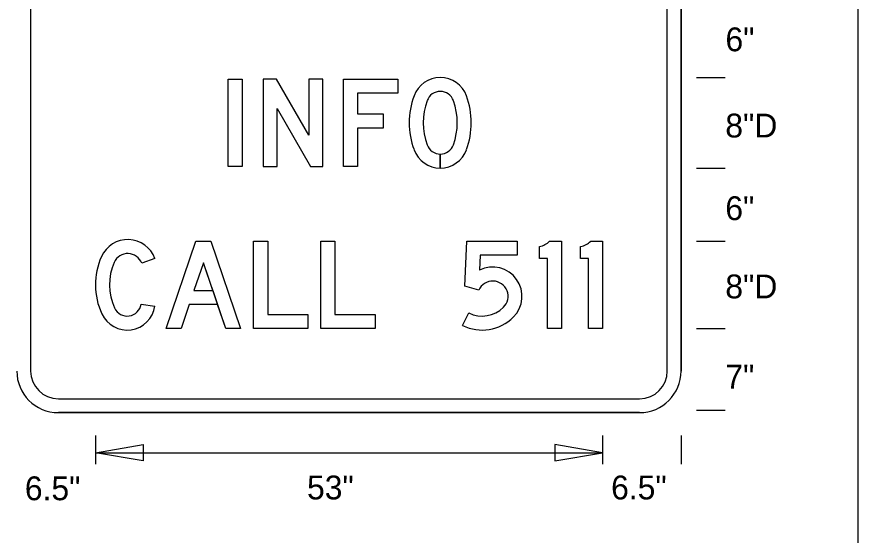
# Model space of a CAD drawing. Extents: x 0 to 770, y 0 to 495.
# Drawn here: x 453.9 to 577.5, y 337 to 413.1 of the extents above; entities that cross this region are included whole.
import ezdxf

# ---------------------------------------------------------------- set-up
doc = ezdxf.new("R2010")
doc.units = 0
for name, color, linetype in [('Default', 7, 'Continuous'), ('Dimension', 7, 'Continuous'), ('GSBWFill', 7, 'Continuous'), ('GSColorFill', 7, 'Continuous'), ('GSDims', 7, 'Continuous'), ('GSOutline', 7, 'Continuous'), ('SheetLines_dp', 7, 'Continuous'), ('TextStructures', 7, 'Continuous')]:
    doc.layers.add(name, color=color, linetype=linetype)

msp = doc.modelspace()

# ---------------------------------------------------------------- linework, layer by layer
at = {"layer": 'Default'}
for p, q in [((455.91, 470.91), (455.91, 361.11)), ((549.45, 361.11), (549.45, 470.91)), ((551.48, 361.11), (551.48, 470.91)), ((551.48, 470.91), (551.48, 361.11)), ((459.98, 357.05), (545.38, 357.05)), ((459.98, 355.01), (545.38, 355.01)), ((545.38, 355.01), (459.98, 355.01))]:
    msp.add_line(p, q, dxfattribs=at)
for centre, radius, start, end in [((459.98, 361.11), 6.1, 180, 270), ((459.98, 361.11), 6.1, 180, 270), ((459.98, 361.11), 4.07, 180, 270), ((545.38, 361.11), 6.1, 270, 0), ((545.38, 361.11), 6.1, 270, 0), ((545.38, 361.11), 4.07, 270, 0)]:
    msp.add_arc(centre, radius, start, end, dxfattribs=at)
at = {"layer": 'Dimension'}
for points in [[(465.43, 349.12), (472.45, 350.31), (472.45, 347.93)], [(539.93, 349.12), (532.91, 350.31), (532.91, 347.93)]]:
    msp.add_lwpolyline(points, close=True, dxfattribs=at)
at = {"layer": 'GSBWFill'}
for p, q in [((516.1, 390.93), (516.1, 392.99)), ((516.1, 392.99), (516.1, 390.93)), ((474.17, 377.64), (472.23, 376.94)), ((472.13, 370.94), (474.17, 370.64)), ((519.38, 367.79), (520.28, 369.64)), ((520.28, 369.64), (520.28, 369.64))]:
    msp.add_line(p, q, dxfattribs=at)
for points in [[(484.95, 404), (487, 404), (487, 391.16), (484.95, 391.16)], [(498.82, 391.16), (498.82, 404), (496.77, 404), (496.77, 395.75), (492.05, 404), (490.09, 404), (490.09, 391.16), (492.14, 391.16), (492.14, 399.7), (497.02, 391.16)], [(509.87, 404), (509.87, 401.95), (503.96, 401.95), (503.96, 398.87), (507.69, 398.87), (507.69, 396.81), (503.96, 396.81), (503.96, 391.16), (501.9, 391.16), (501.9, 404)], [(475.84, 367.36), (480.2, 380.21), (482.39, 380.21), (486.75, 367.36), (484.58, 367.36), (481.29, 377.03), (479.91, 372.95), (482.68, 372.95), (483.38, 370.89), (479.21, 370.89), (478.01, 367.36)], [(490.74, 369.42), (496.64, 369.42), (496.64, 367.36), (488.68, 367.36), (488.68, 380.21), (490.74, 380.21)], [(500.63, 369.42), (506.53, 369.42), (506.53, 367.36), (498.57, 367.36), (498.57, 380.21), (500.63, 380.21)]]:
    msp.add_lwpolyline(points, close=True, dxfattribs=at)
for points in [[(521.76, 373.01), (519.7, 373.59), (520.02, 380.21), (527.41, 380.21), (527.41, 378.15), (521.98, 378.15), (521.87, 375.92)], [(532.16, 380.21), (533.89, 380.21), (533.89, 367.36), (531.84, 367.36), (531.84, 377.64), (530.68, 377.64), (530.68, 379.42)], [(538.2, 380.21), (539.93, 380.21), (539.93, 367.36), (537.88, 367.36), (537.88, 377.64), (536.72, 377.64), (536.72, 379.42)]]:
    msp.add_lwpolyline(points, dxfattribs=at)
for centre, radius, start, end in [((470.18, 376.19), 4.24, 20.0236, 155.9453), ((530.33, 381.87), 2.47, 278.1148, 317.6823), ((536.37, 381.87), 2.47, 278.1148, 317.6823), ((470.18, 376.19), 2.18, 20.0236, 155.9453), ((475.58, 373.78), 10.15, 155.9453, 204.848), ((475.58, 373.78), 8.09, 155.9453, 204.848), ((523.81, 372.08), 4.3, 314.4153, 116.7914), ((523.81, 372.08), 2.25, 314.4153, 155.5257), ((470.1, 371.25), 2.06, 204.848, 351.506), ((470.1, 371.25), 4.11, 204.848, 351.506), ((522.24, 373.69), 4.5, 244.1304, 314.4153), ((522.24, 373.69), 6.55, 244.1304, 314.4153)]:
    msp.add_arc(centre, radius, start, end, dxfattribs=at)
for centre, major_axis, start_param, end_param in [((516.1, 400.12), (0, 4.11), 5.063177, 7.503193), ((516.1, 400.12), (0, 2.06), 5.063177, 7.503193), ((523.03, 397.58), (0, 11.49), 1.220008, 1.921585), ((523.03, 397.58), (0, 9.44), 1.220008, 1.921585), ((509.16, 397.58), (0, 9.44), 4.361601, 5.063177), ((509.16, 397.58), (0, 11.49), 4.361601, 5.063177), ((516.1, 395.04), (0, 4.11), 1.921585, 3.141593), ((516.1, 395.04), (0, 2.06), 1.921585, 3.141593), ((516.1, 395.04), (0, 2.06), 3.141905, 4.361601), ((516.1, 395.04), (0, 4.11), 3.141749, 4.361601)]:
    msp.add_ellipse(centre, major_axis=major_axis, ratio=0.999993, start_param=start_param, end_param=end_param, dxfattribs=at)
at = {"layer": 'GSColorFill'}
for p, q in [((516.1, 390.93), (516.1, 392.99)), ((516.1, 392.99), (516.1, 390.93)), ((474.17, 377.64), (472.23, 376.94)), ((472.13, 370.94), (474.17, 370.64)), ((519.38, 367.79), (520.28, 369.64)), ((520.28, 369.64), (520.28, 369.64))]:
    msp.add_line(p, q, dxfattribs=at)
for points in [[(484.95, 404), (487, 404), (487, 391.16), (484.95, 391.16)], [(498.82, 391.16), (498.82, 404), (496.77, 404), (496.77, 395.75), (492.05, 404), (490.09, 404), (490.09, 391.16), (492.14, 391.16), (492.14, 399.7), (497.02, 391.16)], [(509.87, 404), (509.87, 401.95), (503.96, 401.95), (503.96, 398.87), (507.69, 398.87), (507.69, 396.81), (503.96, 396.81), (503.96, 391.16), (501.9, 391.16), (501.9, 404)], [(475.84, 367.36), (480.2, 380.21), (482.39, 380.21), (486.75, 367.36), (484.58, 367.36), (481.29, 377.03), (479.91, 372.95), (482.68, 372.95), (483.38, 370.89), (479.21, 370.89), (478.01, 367.36)], [(490.74, 369.42), (496.64, 369.42), (496.64, 367.36), (488.68, 367.36), (488.68, 380.21), (490.74, 380.21)], [(500.63, 369.42), (506.53, 369.42), (506.53, 367.36), (498.57, 367.36), (498.57, 380.21), (500.63, 380.21)]]:
    msp.add_lwpolyline(points, close=True, dxfattribs=at)
for points in [[(521.76, 373.01), (519.7, 373.59), (520.02, 380.21), (527.41, 380.21), (527.41, 378.15), (521.98, 378.15), (521.87, 375.92)], [(532.16, 380.21), (533.89, 380.21), (533.89, 367.36), (531.84, 367.36), (531.84, 377.64), (530.68, 377.64), (530.68, 379.42)], [(538.2, 380.21), (539.93, 380.21), (539.93, 367.36), (537.88, 367.36), (537.88, 377.64), (536.72, 377.64), (536.72, 379.42)]]:
    msp.add_lwpolyline(points, dxfattribs=at)
for centre, radius, start, end in [((470.18, 376.19), 4.24, 20.0236, 155.9453), ((530.33, 381.87), 2.47, 278.1148, 317.6823), ((536.37, 381.87), 2.47, 278.1148, 317.6823), ((470.18, 376.19), 2.18, 20.0236, 155.9453), ((475.58, 373.78), 10.15, 155.9453, 204.848), ((475.58, 373.78), 8.09, 155.9453, 204.848), ((523.81, 372.08), 4.3, 314.4153, 116.7914), ((523.81, 372.08), 2.25, 314.4153, 155.5257), ((470.1, 371.25), 2.06, 204.848, 351.506), ((470.1, 371.25), 4.11, 204.848, 351.506), ((522.24, 373.69), 4.5, 244.1304, 314.4153), ((522.24, 373.69), 6.55, 244.1304, 314.4153)]:
    msp.add_arc(centre, radius, start, end, dxfattribs=at)
for centre, major_axis, start_param, end_param in [((516.1, 400.12), (0, 4.11), 5.063177, 7.503193), ((516.1, 400.12), (0, 2.06), 5.063177, 7.503193), ((523.03, 397.58), (0, 11.49), 1.220008, 1.921585), ((523.03, 397.58), (0, 9.44), 1.220008, 1.921585), ((509.16, 397.58), (0, 9.44), 4.361601, 5.063177), ((509.16, 397.58), (0, 11.49), 4.361601, 5.063177), ((516.1, 395.04), (0, 4.11), 1.921585, 3.141593), ((516.1, 395.04), (0, 2.06), 1.921585, 3.141593), ((516.1, 395.04), (0, 2.06), 3.141905, 4.361601), ((516.1, 395.04), (0, 4.11), 3.141749, 4.361601)]:
    msp.add_ellipse(centre, major_axis=major_axis, ratio=0.999993, start_param=start_param, end_param=end_param, dxfattribs=at)
at = {"layer": 'GSDims'}
for p, q in [((553.73, 404.23), (557.98, 404.23)), ((553.73, 390.93), (557.98, 390.93)), ((553.73, 380.21), (557.98, 380.21)), ((553.73, 367.36), (557.98, 367.36)), ((553.73, 355.35), (557.98, 355.35)), ((465.43, 351.67), (465.43, 347.42)), ((465.43, 351.67), (465.43, 347.42)), ((539.93, 351.67), (539.93, 347.42)), ((539.93, 351.67), (539.93, 347.42)), ((551.48, 351.67), (551.48, 347.42)), ((465.43, 349.12), (539.93, 349.12))]:
    msp.add_line(p, q, dxfattribs=at)
at = {"layer": 'GSOutline'}
for p, q in [((474.17, 377.64), (472.23, 376.94)), ((472.13, 370.94), (474.17, 370.64)), ((519.38, 367.79), (520.28, 369.64)), ((520.28, 369.64), (520.28, 369.64))]:
    msp.add_line(p, q, dxfattribs=at)
for points in [[(484.95, 404), (487, 404), (487, 391.16), (484.95, 391.16)], [(498.82, 391.16), (498.82, 404), (496.77, 404), (496.77, 395.75), (492.05, 404), (490.09, 404), (490.09, 391.16), (492.14, 391.16), (492.14, 399.7), (497.02, 391.16)], [(509.87, 404), (509.87, 401.95), (503.96, 401.95), (503.96, 398.87), (507.69, 398.87), (507.69, 396.81), (503.96, 396.81), (503.96, 391.16), (501.9, 391.16), (501.9, 404)], [(479.21, 370.89), (478.01, 367.36), (475.84, 367.36), (480.2, 380.21), (482.39, 380.21), (486.75, 367.36), (484.58, 367.36), (483.38, 370.89)], [(490.74, 369.42), (496.64, 369.42), (496.64, 367.36), (488.68, 367.36), (488.68, 380.21), (490.74, 380.21)], [(500.63, 369.42), (506.53, 369.42), (506.53, 367.36), (498.57, 367.36), (498.57, 380.21), (500.63, 380.21)], [(479.91, 372.95), (482.68, 372.95), (481.29, 377.03)]]:
    msp.add_lwpolyline(points, close=True, dxfattribs=at)
for points in [[(521.76, 373.01), (519.7, 373.59), (520.02, 380.21), (527.41, 380.21), (527.41, 378.15), (521.98, 378.15), (521.87, 375.92)], [(532.16, 380.21), (533.89, 380.21), (533.89, 367.36), (531.84, 367.36), (531.84, 377.64), (530.68, 377.64), (530.68, 379.42)], [(538.2, 380.21), (539.93, 380.21), (539.93, 367.36), (537.88, 367.36), (537.88, 377.64), (536.72, 377.64), (536.72, 379.42)]]:
    msp.add_lwpolyline(points, dxfattribs=at)
for centre, radius, start, end in [((470.18, 376.19), 4.24, 20.0236, 155.9453), ((530.33, 381.87), 2.47, 278.1148, 317.6823), ((536.37, 381.87), 2.47, 278.1148, 317.6823), ((470.18, 376.19), 2.18, 20.0236, 155.9453), ((475.58, 373.78), 10.15, 155.9453, 204.848), ((475.58, 373.78), 8.09, 155.9453, 204.848), ((523.81, 372.08), 4.3, 314.4153, 116.7914), ((523.81, 372.08), 2.25, 314.4153, 155.5257), ((470.1, 371.25), 2.06, 204.848, 351.506), ((470.1, 371.25), 4.11, 204.848, 351.506), ((522.24, 373.69), 4.5, 244.1304, 314.4153), ((522.24, 373.69), 6.55, 244.1304, 314.4153)]:
    msp.add_arc(centre, radius, start, end, dxfattribs=at)
for centre, major_axis, start_param, end_param in [((516.1, 400.12), (0, 4.11), 5.063177, 7.503193), ((516.1, 400.12), (0, 2.06), 5.063177, 7.503193), ((523.03, 397.58), (0, 11.49), 1.220008, 1.921585), ((523.03, 397.58), (0, 9.44), 1.220008, 1.921585), ((509.16, 397.58), (0, 9.44), 4.361601, 5.063177), ((509.16, 397.58), (0, 11.49), 4.361601, 5.063177), ((516.1, 395.04), (0, 4.11), 1.921585, 4.361601), ((516.1, 395.04), (0, 2.06), 1.921585, 4.361601)]:
    msp.add_ellipse(centre, major_axis=major_axis, ratio=0.999993, start_param=start_param, end_param=end_param, dxfattribs=at)
at = {"layer": 'SheetLines_dp'}
msp.add_line((577.5, 0), (577.5, 495), dxfattribs=at)

# ---------------------------------------------------------------- texts
at = {"layer": 'TextStructures'}
for s, p in [('6"', (558, 408.08)), ('8"D', (557.98, 395.42)), ('6"', (557.98, 383.28)), ('8"D', (557.98, 371.79)), ('7"', (557.98, 358.53)), ('6.5"', (455.06, 342.14)), ('53"', (496.52, 342.26)), ('6.5"', (541.2, 342.26))]:
    msp.add_text(s, height=3.5, dxfattribs=at).set_placement(p)

doc.saveas('drawing.dxf')
